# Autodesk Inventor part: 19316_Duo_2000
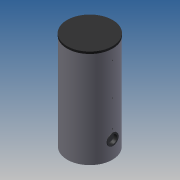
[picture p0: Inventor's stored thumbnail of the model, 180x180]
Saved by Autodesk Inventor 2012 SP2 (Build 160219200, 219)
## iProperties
allow_slope_adjustment: 0 ul
connection_type: 13 ul
flow_configuration2: 1 ul
flow_direction: 2 ul
loss_method: 0 ul
radius: 12,250 mm
radius: 28,500 mm
Created: 2014-05
Part Number: 19316_Duo_2000
Material: Default
Document SubType Name: Modeling
Designer: michel
Density: 1 g/cm^3
radius: 15,375 mm
description: 0:0:19316_Duo_2000
manufacturer: 0:0:Flamco Group
model: 0:0:Duo 2000
url: 0:0:www.flamcogroup.com
radius: 9,500 mm
Author: michel
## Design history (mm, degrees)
sketch "Sketch1"
  geometry: C1 r 550 at (0, 0); 1 further point
  constraints: 1 centre point, 1 coincident
  dimensions: "d0" = 1100 diameter of C1
extrude "Extrusion1" new body sketch "Sketch1" distance "d1" = 2400; taper "d2" = 0 deg
sketch "Sketch2"
  geometry: L1 (-550, 2400)-(550, 2400) reference; L2 (-550, 0)-(550, 0) reference; L3 (550, 0)-(550, 2400) reference; L4 (550, 2400)-(555, 2400); L5 (555, 2400)-(555, 2350); L6 (555, 2350)-(550, 2350); L7 (550, 2350)-(550, 2400); L8 (0, -464)-(0, 2784) reference; 1 further point
  constraints: 8 end point, 2 parallel, 1 horizontal, 1 perpendicular
  dimensions: "d3" = 5 distance of L5.end L6.end; "d4" = 50 distance of L4.end L5.end
revolve "Revolution1" sketch "Sketch2" stored, may be unused: angle "d5" = 90 deg
workplane "Work Plane1"
workplane "Work Plane2"
workplane "Work Plane3"
workplane "Work Plane4"
workplane "Work Plane5"
workplane "Work Plane6"
workplane "Work Plane11"
workplane "Work Plane12"
workplane "Work Plane13"
sketch "Sketch3"
  geometry: L1 (771.4, 2255)-(-771.4, 2255) reference; L2 (771.4, 1755)-(-771.4, 1755) reference; L3 (771.4, 1575)-(-771.4, 1575) reference; L4 (771.4, 455)-(-771.4, 455) reference; L5 (771.4, 105)-(-771.4, 105) reference; L6 (550, 0)-(550, 2350) reference; L7 (550, 2255)-(510, 2255); L8 (510, 2255)-(510, 2284.805); L9 (510, 2284.805)-(550, 2284.805); L10 (550, 1755)-(510, 1755); L11 (510, 1755)-(510, 1771.625); L12 (510, 1771.625)-(550, 1771.625); L13 (550, 1771.625)-(550, 1755); L14 (335, 2226.5)-(335, 2225.195); L15 (335, 2225.195)-(551, 2225.195); L16 (551, 2225.195)-(551, 2226.5); L17 (551, 2226.5)-(335, 2226.5); L18 (510, 1575)-(510, 1604.805); L19 (550, 1575)-(510, 1575); L20 (510, 1604.805)-(550, 1604.805); L21 (550, 1604.805)-(550, 1575); L22 (335, 1546.5)-(335, 1545.195); L23 (335, 1545.195)-(551, 1545.195); L24 (551, 1545.195)-(551, 1546.5); L25 (551, 1546.5)-(335, 1546.5); L26 (510, 484.805)-(550, 484.805); L27 (510, 455)-(510, 484.805); L28 (550, 455)-(510, 455); L29 (550, 484.805)-(550, 455); L30 (551, 426.5)-(335.165, 426.5); L31 (335.165, 426.5)-(335.165, 425.195); L32 (335.165, 425.195)-(551, 425.195); L33 (551, 425.195)-(551, 426.5); L34 (510, 134.805)-(550, 134.805); L35 (510, 105)-(510, 134.805); L36 (550, 105)-(510, 105); L37 (550, 134.805)-(550, 105); L38 (551, 76.5)-(335, 76.5); L39 (335, 76.5)-(335, 75.195); L40 (335, 75.195)-(551, 75.195); L41 (551, 75.195)-(551, 76.5); L42 (335, 1739.625)-(335, 1738.375); L43 (551, 1738.375)-(551, 1739.625); L44 (551, 1739.625)-(335, 1739.625); L45 (-777, 2100)-(777, 2100) reference; L46 (771.4, 1300)-(-771.4, 1300) reference; L47 (-550, 0)-(-550, 2350) reference; L48 (-550, 2100)-(-510, 2100); L49 (-510, 2100)-(-510, 2110.475); L50 (-510, 2110.475)-(-550, 2110.475); L51 (-550, 2110.475)-(-550, 2100); L52 (-551, 2089.525)-(-335, 2089.525); L53 (-335, 2089.525)-(-335, 2090.5); L54 (-335, 2090.5)-(-551, 2090.5); L55 (-551, 2090.5)-(-551, 2089.525); L56 (-550, 1300)-(-335, 1300); L57 (-335, 1300)-(-335, 1313.22); L58 (-335, 1313.22)-(-550, 1313.22); L59 (-550, 1313.22)-(-550, 1300); L60 (-551, 1286.78)-(-335, 1286.78); L61 (-335, 1286.78)-(-335, 1287.75); L62 (-335, 1287.75)-(-551, 1287.75); L63 (-551, 1287.75)-(-551, 1286.78); L64 (550, 2284.805)-(550, 2255)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; 2 further points
  constraints: 128 end point, 20 parallel, 9 horizontal, 9 perpendicular, 8 point on line, 1 collinear
  dimensions: "d19" = 40 distance of L8.end L9.end; "d21" = 40 distance of L11.end L12.end; "d70" = 29.805 distance between parallel lines of L1 L9; "d73" = 40 distance of L18.end L20.end; "d74" = 40 distance of L26.start L26.end; "d75" = 40 distance of L34.start L34.end; "d76" = 29.805 distance between parallel lines of L3 L20; "d85" = 16.625 distance between parallel lines of L2 L12; "d108" = 29.805 distance between parallel lines of L1 L15 (derived); "d109" = 1.305 distance between parallel lines of L17 L15 (derived); "d110" = 16.625 distance between parallel lines of L10 L12 (= d85); "d113" = 29.805 distance between parallel lines of L19 L20 (= d76); "d114" = 29.805 distance between parallel lines of L23 L3 (derived); "d115" = 1.305 distance between parallel lines of L25 L23 (derived); "d116" = 29.805 distance between parallel lines of L4 L26; "d117" = 29.805 distance of L26.start L27.start (= d116); "d118" = 29.805 distance between parallel lines of L32 L4 (derived); "d119" = 1.305 distance between parallel lines of L30 L32 (derived); "d120" = 29.805 distance from line of L34 L35.start (= d121); "d121" = 29.805 distance between parallel lines of L5 L34; "d122" = 29.805 distance between parallel lines of L40 L5 (derived); "d123" = 1.305 distance between parallel lines of L38 L40 (derived); "d129" = 40 distance of L50.end L49.end; "d130" = 10.475 distance of L49.end L48.end; "d131" = 10.475 distance between parallel lines of L45 L52; "d132" = 0.975 distance between parallel lines of L54 L52; "d134" = 13.22 distance between parallel lines of L46 L58; "d135" = 13.22 distance between parallel lines of L46 L60 (derived); "d136" = 0.97 distance between parallel lines of L62 L60 (derived); "d154" = 1 distance between parallel lines of L47 L55; "d155" = 1 distance between parallel lines of L47 L63; "d157" = 1 distance between parallel lines of L6 L16; "d158" = 0 distance between parallel lines of L6 L13; "d159" = 1 distance between parallel lines of L6 L43; "d160" = 0 distance between parallel lines of L6 L21; "d161" = 1 distance between parallel lines of L6 L24; "d162" = 0 distance between parallel lines of L6 L29; "d163" = 1 distance between parallel lines of L6 L33; "d164" = 0 distance between parallel lines of L6 L37; "d165" = 1 distance between parallel lines of L6 L41; "d166" = 16.625 distance between parallel lines of L65 L2 (derived); "d167" = 1.25 distance between parallel lines of L44 L65 (derived); "d173" = 0 distance between parallel lines of L6 L64; "d181" = 40 distance of L69.end L68.end; "d182" = 13.22 distance of L68.end L67.end; "d183" = 13.22 distance between parallel lines of L66 L73 (derived); "d184" = 0.97 distance between parallel lines of L71 L73 (derived); "d185" = 1 distance between parallel lines of L47 L74
revolve "Revolution2" stored, may be unused: angle "d23" = 90 deg
sketch "Sketch5"
  geometry: L1 (-550, 0)-(-550, 2350) reference; L2 (-550, 0)-(-550, 435); L3 (-220, 435)-(-594, 435); L4 (-550, 435)-(-562.5, 435); L5 (-562.5, 435)-(-562.5, 575); L6 (-562.5, 575)-(-550, 575); L7 (-550, 575)-(-550, 435); L8 (-550, 0)-(550, 0) reference; 1 further point
  constraints: 12 end point, 2 parallel, 2 perpendicular, 1 horizontal, 1 point on line
  dimensions: "d35" = 435 distance of L1.start L2.end; "d36" = 12.5 distance of L5.end L6.end; "d37" = 140 distance of L4.end L5.end; "d124" = 435 distance between parallel lines of L8 L3 (= d35)
revolve "Revolution7" sketch "Sketch5" stored, may be unused: angle "d38" = 90 deg
sketch "Sketch6"
  geometry: C1 r 122.5 at (0, 0); A1 r 140 centre (0, 0) between (140, 0) and (-140, 0) reference; 1 further point
  constraints: 1 centre point, 1 coincident
  dimensions: "d39" = 245 diameter of C1
extrude "Extrusion3" join sketch "Sketch6" stored distance "d40" = 40; taper "d41" = 0 deg
sketch "Sketch7"
  geometry: C1 r 140 at (0, 0) reference; C2 r 102.5 at (0, 0); 1 further point
  constraints: 1 centre point, 1 coincident
  dimensions: "d42" = 205 diameter of C2
extrude "Extrusion4" cut sketch "Sketch7" distance "d43" = 80; taper "d44" = 0 deg
revolve "Revolution9" stored, may be unused: angle "d69" = 90 deg
revolve "Revolution10" stored, may be unused: angle "d92" = 90 deg
revolve "Revolution11" stored, may be unused: angle "d93" = 90 deg
revolve "Revolution12" stored, may be unused: angle "d94" = 90 deg
revolve "Revolution13" stored, may be unused: angle "d95" = 90 deg
revolve "Revolution14" stored, may be unused: angle "d96" = 90 deg
revolve "Revolution15" stored, may be unused: angle "d97" = 90 deg
revolve "Revolution16" stored, may be unused: angle "d98" = 90 deg
revolve "Revolution17" stored, may be unused: angle "d99" = 90 deg
revolve "Revolution18" stored, may be unused: angle "d138" = 90 deg
revolve "Revolution19" stored, may be unused: angle "d139" = 90 deg
revolve "Revolution20" stored, may be unused: angle "d140" = 90 deg
revolve "Revolution21" stored, may be unused: angle "d141" = 90 deg
revolve "Revolution22" stored, may be unused: angle "d186" = 90 deg
revolve "Revolution23" stored, may be unused: angle "d187" = 90 deg
body "Solid1"
node "Projected Loop1"
other parameters: "d12" = 0, "d188" = -2255, "d189" = -1755, "d190" = -1575, "d191" = -455, "d192" = -105
